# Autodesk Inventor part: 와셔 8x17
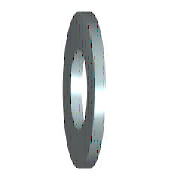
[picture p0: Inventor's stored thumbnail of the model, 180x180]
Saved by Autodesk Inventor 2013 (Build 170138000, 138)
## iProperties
IsCustomPart: 1
Created: 2012-02
Part Number: 와셔 8x17
Material: 강철, 연강
Description: 평면 와셔
Document SubType Name: Modeling
Standard: KS B 1326
Designer: mduedu
Standards Organization: KS
Language: ko-KR
Size Designation: 8x17
Categories: <MemberInstance><Categories><Category DisplayName="조임쇠" InternalName="e4da775c-781d-43d5-af7c-5136215cf5a6" Mnemonic="FSTN"><Category DisplayName="와셔" InternalN
Density: 1 g/cm^3
Author: mduedu
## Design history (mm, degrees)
sketch "스케치"
  geometry: C1 r 8.5 at (0, 0); C2 r 4.2 at (0, 0); 1 further point
  constraints: 2 centre point, 2 coincident
  dimensions: "d0" = 8.4 diameter of C2 (= SD1); "d1" = 17 diameter of C1 (= SD2)
extrude "본체" new body sketch "스케치" distance "d2" = 1.6 (= SD); taper "d3" = 0 deg
workaxis "Work Axis1"
workplane "Work Plane1"
body "Solid1"
other parameters: "SD1" = 8.4 [user parameter; used in 1 equation term], "SD2" = 17 [user parameter; used in 1 equation term], "SD" = 1.6 [user parameter; used in 1 equation term], "d4" = 0, "d5" = 0, "d6" = 0, "d7" = 0, "NND" = 8 [user parameter]
